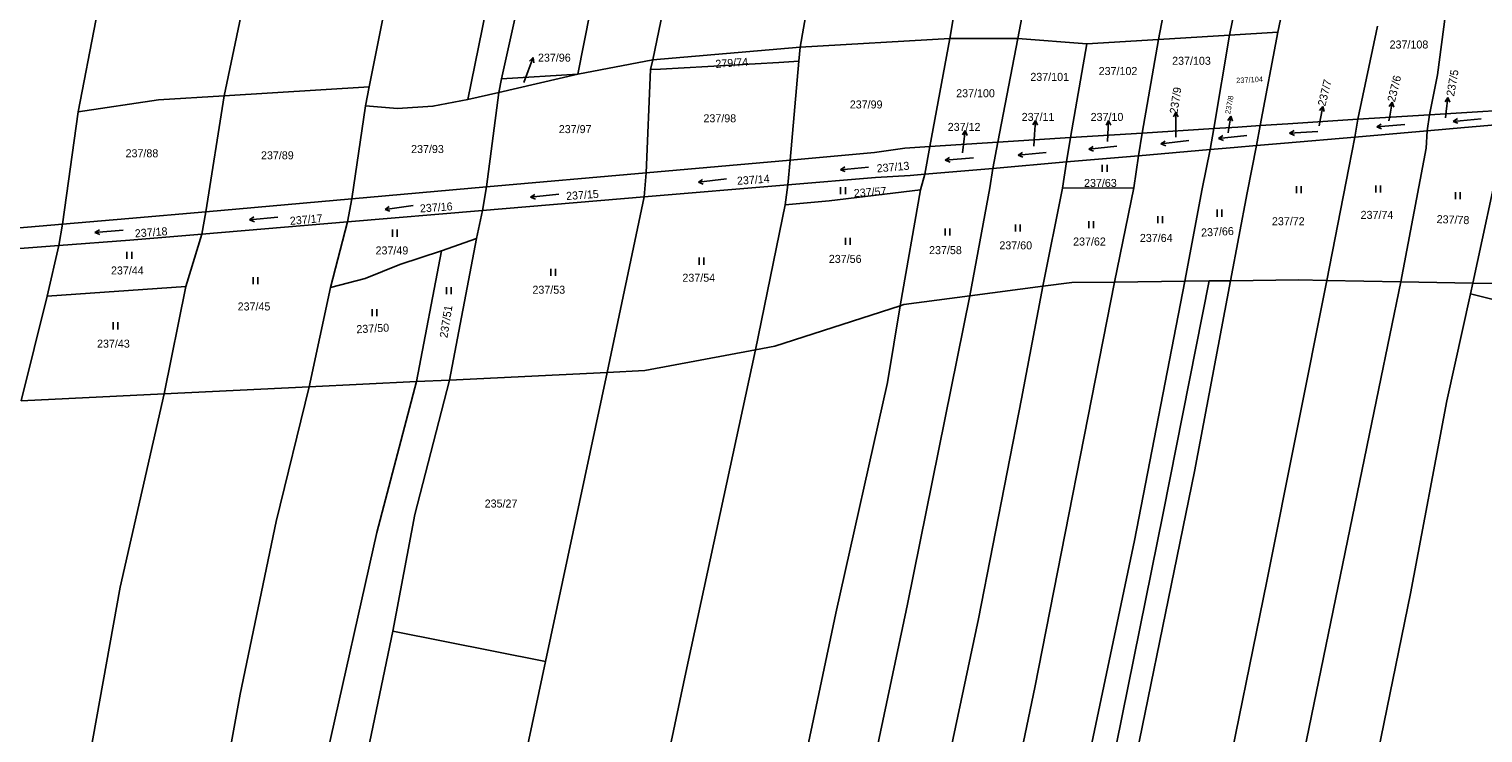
# Model space of a CAD drawing. Extents: x -755528 to -748832, y -1118122 to -1111095.
# Drawn here: x -753275.1 to -752966.3, y -1115050.1 to -1114900.7 of the extents above; entities that cross this region are included whole.
import ezdxf

# ---------------------------------------------------------------- set-up
doc = ezdxf.new("R2010")
doc.units = 0
for name, color, linetype in [('DZ_DO_PUPFL', 7, 'Continuous'), ('DZ_NAD_ZPF', 7, 'Continuous'), ('legenda barvy', 7, 'Continuous'), ('TZ_UMVŽST', 7, 'Continuous')]:
    doc.layers.add(name, color=color, linetype=linetype)

msp = doc.modelspace()

# ---------------------------------------------------------------- linework, layer by layer
at = {"layer": 'DZ_NAD_ZPF'}
for p, q in [((-753020.14, -1114901.94), (-753035.22, -1114902.86)), ((-753023.47, -1114921.78), (-753020.14, -1114901.94)), ((-753009.89, -1114901.31), (-753020.14, -1114901.94)), ((-753013.68, -1114921.16), (-753009.89, -1114901.31)), ((-752988.72, -1114900.02), (-752992.9, -1114919.83)), ((-753111.37, -1114904.48), (-753142.68, -1114907.21)), ((-753111.37, -1114904.48), (-753111.63, -1114907.51)), ((-753079.6, -1114902.69), (-753111.37, -1114904.48)), ((-753083.82, -1114925.62), (-753079.6, -1114902.69)), ((-753065.11, -1114902.7), (-753079.6, -1114902.69)), ((-753069.4, -1114924.7), (-753065.11, -1114902.7)), ((-753050.47, -1114903.79), (-753065.11, -1114902.7)), ((-753053.95, -1114923.72), (-753050.47, -1114903.79)), ((-753035.22, -1114902.86), (-753050.47, -1114903.79)), ((-753038.69, -1114922.75), (-753035.22, -1114902.86)), ((-753142.68, -1114907.21), (-753158.58, -1114910.23)), ((-753143.11, -1114909.28), (-753142.68, -1114907.21)), ((-753113.45, -1114928.48), (-753111.63, -1114907.51)), ((-753175.36, -1114914.1), (-753158.58, -1114910.23)), ((-753174.8, -1114911.22), (-753175.36, -1114914.1)), ((-753158.58, -1114910.23), (-753174.8, -1114911.22)), ((-753144.06, -1114931.18), (-753143.11, -1114909.28)), ((-753202.86, -1114912.96), (-753233.7, -1114914.85)), ((-753203.65, -1114916.94), (-753202.86, -1114912.96)), ((-753175.36, -1114914.1), (-753181.91, -1114915.59)), ((-753177.98, -1114934.18), (-753175.36, -1114914.1)), ((-753237.55, -1114939.45), (-753233.7, -1114914.85)), ((-753206.55, -1114936.71), (-753203.65, -1114916.94)), ((-753268.06, -1114942.09), (-753264.7, -1114918.22)), ((-752992.9, -1114919.83), (-752993.58, -1114923.59)), ((-752977.72, -1114918.87), (-752992.9, -1114919.83)), ((-752977.72, -1114918.87), (-752978.17, -1114922.25)), ((-753053.95, -1114923.72), (-753069.4, -1114924.7)), ((-753053.95, -1114923.72), (-753054.8, -1114928.89)), ((-753038.69, -1114922.75), (-753053.95, -1114923.72)), ((-753038.69, -1114922.75), (-753039.49, -1114927.56)), ((-753023.47, -1114921.78), (-753038.69, -1114922.75)), ((-753023.47, -1114921.78), (-753024.25, -1114926.24)), ((-753013.68, -1114921.16), (-753014.47, -1114925.4)), ((-752993.58, -1114923.59), (-752978.17, -1114922.25)), ((-753083.82, -1114925.62), (-753084.91, -1114931.5)), ((-753069.4, -1114924.7), (-753083.82, -1114925.62)), ((-753069.4, -1114924.7), (-753070.43, -1114930.25)), ((-753039.49, -1114927.56), (-753024.25, -1114926.24)), ((-753113.45, -1114928.48), (-753144.06, -1114931.18)), ((-753113.45, -1114928.48), (-753114, -1114933.76)), ((-753054.8, -1114928.89), (-753070.43, -1114930.25)), ((-753055.67, -1114934.43), (-753054.8, -1114928.89)), ((-753054.8, -1114928.89), (-753039.49, -1114927.56)), ((-753040.49, -1114934.41), (-753039.49, -1114927.56)), ((-753144.06, -1114931.18), (-753177.98, -1114934.18)), ((-753144.06, -1114931.18), (-753144.47, -1114936.32)), ((-753085.79, -1114934.81), (-753084.91, -1114931.5)), ((-753070.43, -1114930.25), (-753084.91, -1114931.5)), ((-753177.98, -1114934.18), (-753206.55, -1114936.71)), ((-753177.98, -1114934.18), (-753178.79, -1114939.2)), ((-753114, -1114933.76), (-753144.47, -1114936.32)), ((-753114.57, -1114937.97), (-753114, -1114933.76)), ((-753090.14, -1114959.41), (-753085.79, -1114934.81)), ((-753059.79, -1114955.29), (-753055.67, -1114934.43)), ((-753040.49, -1114934.41), (-753055.67, -1114934.43)), ((-753044.61, -1114954.39), (-753040.49, -1114934.41)), ((-753206.55, -1114936.71), (-753237.55, -1114939.45)), ((-753206.55, -1114936.71), (-753207.49, -1114941.6)), ((-753207.49, -1114941.6), (-753178.79, -1114939.2)), ((-753180.08, -1114945.16), (-753178.79, -1114939.2)), ((-753144.47, -1114936.32), (-753178.79, -1114939.2)), ((-753152.36, -1114973.59), (-753144.47, -1114936.32)), ((-753120.85, -1114968.78), (-753114.57, -1114937.97)), ((-753268.06, -1114942.09), (-753268.82, -1114946.63)), ((-753237.55, -1114939.45), (-753238.46, -1114944.2)), ((-753207.49, -1114941.6), (-753238.46, -1114944.2)), ((-753211.09, -1114955.55), (-753207.49, -1114941.6)), ((-753241.8, -1114955.31), (-753238.46, -1114944.2)), ((-753187.51, -1114947.77), (-753180.08, -1114945.16)), ((-753185.8, -1114975.2), (-753180.08, -1114945.16)), ((-753271.25, -1114957.38), (-753268.82, -1114946.63)), ((-753192.84, -1114975.54), (-753187.51, -1114947.77)), ((-753029.64, -1114954.22), (-753044.61, -1114954.39)), ((-753024.49, -1114954.16), (-753029.64, -1114954.22)), ((-753019.97, -1114954.11), (-753024.49, -1114954.16)), ((-752983.78, -1114954.34), (-752999.53, -1114954.05)), ((-752968.48, -1114954.62), (-752983.78, -1114954.34)), ((-752969, -1114956.89), (-752968.48, -1114954.62)), ((-752968.48, -1114954.62), (-752877, -1114956.31)), ((-753276.79, -1114979.6), (-753271.25, -1114957.38)), ((-753241.8, -1114955.31), (-753271.25, -1114957.38)), ((-753246.42, -1114978.13), (-753241.8, -1114955.31)), ((-753215.61, -1114976.64), (-753211.09, -1114955.55)), ((-753059.79, -1114955.29), (-753075.3, -1114957.32)), ((-752882.52, -1114978.45), (-752969, -1114956.89)), ((-753192.84, -1114975.54), (-753215.61, -1114976.64)), ((-753185.8, -1114975.2), (-753192.84, -1114975.54)), ((-753152.36, -1114973.59), (-753185.8, -1114975.2)), ((-753152.36, -1114973.59), (-753165.42, -1115034.99)), ((-753246.42, -1114978.13), (-753276.79, -1114979.6)), ((-753215.61, -1114976.64), (-753246.42, -1114978.13)), ((-753165.42, -1115034.99), (-753197.88, -1115028.53))]:
    msp.add_line(p, q, dxfattribs=at)
for points in [[(-753233.7, -1114914.85), (-753217.47, -1114837.62), (-753202.57, -1114766.08), (-753187.86, -1114697.77), (-753179.3, -1114653.45), (-753168.66, -1114603.79), (-753159.07, -1114559.65), (-753147.81, -1114508.95), (-753135.86, -1114458.16), (-753132.99, -1114439.92), (-753119.03, -1114364.97), (-753111.96, -1114332.42), (-753103.7, -1114299.27)], [(-753202.86, -1114912.96), (-753196.54, -1114881.1), (-753179.94, -1114804.74), (-753172.5, -1114766.42), (-753164.58, -1114726.12), (-753158.67, -1114699.35), (-753147.41, -1114652.62), (-753133.93, -1114587.99), (-753116.45, -1114506.67), (-753099.09, -1114423.78), (-753085.35, -1114358.88), (-753073.79, -1114304.82)], [(-753181.91, -1114915.59), (-753175, -1114881.47), (-753166.34, -1114839.97), (-753151.09, -1114766.66), (-753147.42, -1114748.58), (-753124.96, -1114651.85), (-753111.4, -1114582.84), (-753088.5, -1114479.57), (-753082.41, -1114445.74), (-753066.82, -1114371.23), (-753053.46, -1114308.6)], [(-753174.8, -1114911.22), (-753161.71, -1114852.23), (-753150.45, -1114796.76), (-753144.34, -1114766.73), (-753129.5, -1114697.6), (-753107.35, -1114597.98), (-753086.49, -1114497.53), (-753065.55, -1114394.92), (-753055.27, -1114343.56), (-753047.11, -1114309.78)], [(-753079.6, -1114902.69), (-753076.05, -1114881.54), (-753064.88, -1114833.75), (-753052.18, -1114771.34), (-753045.81, -1114738.36), (-753034.75, -1114687.32), (-753019.74, -1114619.92), (-753015.56, -1114599.37), (-753012.63, -1114588.54), (-752993.34, -1114497.31), (-752981.27, -1114437.96)], [(-753065.11, -1114902.7), (-753059.93, -1114875.41), (-753047.44, -1114822.82), (-753037.25, -1114772.48), (-753020.44, -1114690.21), (-752998.89, -1114596.67), (-752973.28, -1114483.85)], [(-753035.22, -1114902.86), (-753030.76, -1114879.49), (-753016.74, -1114820.75), (-753007.19, -1114774.77), (-752985.34, -1114668.69), (-752977.68, -1114633.44), (-752960.36, -1114552.68), (-752959.4, -1114549.77)], [(-753020.14, -1114901.94), (-753015.82, -1114880.89), (-753004.67, -1114831.04), (-752992.55, -1114775.89), (-752973.57, -1114684.2), (-752964.06, -1114637.71), (-752949.38, -1114576.99)], [(-753093.45, -1114602.23), (-753114.66, -1114693.33), (-753129.66, -1114766.9), (-753132.52, -1114779.2), (-753140.82, -1114819.96), (-753149.27, -1114863.31), (-753158.58, -1114910.23)], [(-753009.89, -1114901.31), (-752994.51, -1114828.43), (-752983.39, -1114776.59), (-752968.12, -1114704.27), (-752953.14, -1114634.3), (-752944.93, -1114599.94)], [(-753264.7, -1114918.22), (-753253.41, -1114859.98), (-753238.85, -1114790.7), (-753233.89, -1114765.73)], [(-753112.36, -1114767.73), (-753127.45, -1114836.94), (-753135.8, -1114873.94), (-753142.68, -1114907.21)], [(-753111.37, -1114904.48), (-753106.02, -1114874.19), (-753096.27, -1114830.76), (-753083.04, -1114769.21)], [(-752977.72, -1114918.87), (-752976.01, -1114910.37), (-752974.31, -1114897.47)], [(-753111.63, -1114907.51), (-753115.91, -1114907.77), (-753141.01, -1114909.15), (-753143.11, -1114909.28)], [(-753233.7, -1114914.85), (-753247.65, -1114915.71), (-753264.7, -1114918.22)], [(-753181.91, -1114915.59), (-753189.35, -1114917.06), (-753196.89, -1114917.54), (-753203.65, -1114916.94)], [(-752960.63, -1114917.78), (-752969.79, -1114918.36), (-752977.72, -1114918.87)], [(-753013.68, -1114921.16), (-753007.8, -1114920.78), (-752992.9, -1114919.83)], [(-752978.17, -1114922.25), (-752970.29, -1114921.57), (-752961.19, -1114920.78)], [(-753013.68, -1114921.16), (-753018.37, -1114921.46), (-753023.47, -1114921.78)], [(-752993.58, -1114923.59), (-753008.51, -1114924.88), (-753014.47, -1114925.4)], [(-752999.53, -1114954.05), (-752994.82, -1114930.13), (-752993.58, -1114923.59)], [(-752983.78, -1114954.34), (-752978.38, -1114925.93), (-752978.17, -1114922.25)], [(-753083.82, -1114925.62), (-753089.16, -1114925.96), (-753095.54, -1114926.9), (-753113.45, -1114928.48)], [(-753029.64, -1114954.22), (-753026, -1114934.62), (-753024.25, -1114926.24)], [(-753024.25, -1114926.24), (-753019.21, -1114925.81), (-753014.47, -1114925.4)], [(-753019.97, -1114954.11), (-753016.4, -1114935.42), (-753014.47, -1114925.4)], [(-752962, -1114924.6), (-752962.3, -1114926.03), (-752968.48, -1114954.62)], [(-753114, -1114933.76), (-753095.39, -1114932.2), (-753087.96, -1114931.76), (-753084.91, -1114931.5)], [(-753075.3, -1114957.32), (-753071.1, -1114934.41), (-753070.43, -1114930.25)], [(-753085.79, -1114934.81), (-753105.21, -1114937.15), (-753114.57, -1114937.97)], [(-753268.06, -1114942.09), (-753297.83, -1114944.61), (-753329.47, -1114947.29)], [(-753237.55, -1114939.45), (-753253.91, -1114940.89), (-753268.06, -1114942.09)], [(-753268.82, -1114946.63), (-753253.71, -1114945.48), (-753238.46, -1114944.2)], [(-753330.11, -1114951.34), (-753298.37, -1114948.9), (-753268.82, -1114946.63)], [(-753211.09, -1114955.55), (-753203.72, -1114953.66), (-753196.35, -1114950.65), (-753187.51, -1114947.77)], [(-753142.13, -1115429.02), (-753113.35, -1115286.36), (-753098.91, -1115217.03), (-753079.17, -1115125.01), (-753061.54, -1115040.52), (-753044.61, -1114954.39)], [(-753127.57, -1115428.31), (-753109.02, -1115343.31), (-753101.95, -1115305.88), (-753088.18, -1115233.5), (-753082.58, -1115208.88), (-753068.45, -1115142.47), (-753054.82, -1115077.88), (-753040.32, -1115009.27), (-753029.64, -1114954.22)], [(-753121.98, -1115428.03), (-753113.5, -1115387.63), (-753100.32, -1115322.58), (-753082.33, -1115233.25), (-753071.4, -1115180.79), (-753054.16, -1115101.79), (-753034.24, -1115003.46), (-753024.49, -1114954.16)], [(-753116.71, -1115427.77), (-753105.87, -1115373.64), (-753091.48, -1115301.38), (-753073.35, -1115211.52), (-753044.22, -1115075.89), (-753027.58, -1114994.65), (-753019.97, -1114954.11)], [(-753087.93, -1115385.88), (-753082.85, -1115356.32), (-753066.21, -1115276.38), (-753045.09, -1115175.92), (-753031.36, -1115111.65), (-753012.25, -1115017.92), (-752999.53, -1114954.05)], [(-753074.17, -1115385.26), (-753051.79, -1115280.52), (-753019.64, -1115128.38), (-752988.43, -1114977.02), (-752983.78, -1114954.34)], [(-753044.61, -1114954.39), (-753053.64, -1114954.49), (-753059.79, -1114955.29)], [(-752999.53, -1114954.05), (-753005.53, -1114953.94), (-753019.97, -1114954.11)], [(-753173.17, -1115430.68), (-753165.93, -1115395.55), (-753157.07, -1115356.14), (-753143.95, -1115293.66), (-753132.77, -1115235.62), (-753120.85, -1115176.85), (-753113.19, -1115143.15), (-753098.74, -1115070.99), (-753088.53, -1115022.81), (-753075.3, -1114957.32)], [(-753157.12, -1115429.79), (-753150.72, -1115394.51), (-753138.44, -1115339.24), (-753127.69, -1115287.77), (-753108.52, -1115190.37), (-753090.15, -1115104.28), (-753073.5, -1115025.89), (-753064.38, -1114979.16), (-753059.79, -1114955.29)], [(-753075.3, -1114957.32), (-753089.36, -1114959.16), (-753090.14, -1114959.41)], [(-752969, -1114956.89), (-752973.99, -1114979.61), (-752981.76, -1115020.52), (-753009.84, -1115157.88), (-753021.45, -1115211.53), (-753030.12, -1115252.85), (-753038.41, -1115288.88), (-753048.31, -1115334.89), (-753058.01, -1115384.53)], [(-753187.21, -1115431.46), (-753171.22, -1115354.98), (-753155.73, -1115279.97), (-753131.55, -1115155.67), (-753126.89, -1115133.75), (-753114.32, -1115074.76), (-753103.75, -1115024.73), (-753092.8, -1114975.75), (-753090.14, -1114959.41)], [(-753090.14, -1114959.41), (-753116.72, -1114968), (-753120.85, -1114968.78)], [(-753217.8, -1115433.14), (-753211.03, -1115398.97), (-753197.49, -1115336.74), (-753189.65, -1115300.03), (-753181.32, -1115255.47), (-753169.71, -1115196.97), (-753161.38, -1115155.22), (-753150.59, -1115108.84), (-753147.28, -1115092.2), (-753135.87, -1115038.32), (-753120.85, -1114968.78)], [(-753120.85, -1114968.78), (-753144.35, -1114973.2), (-753152.36, -1114973.59)], [(-753289.44, -1115425.79), (-753270.46, -1115352.32), (-753253.52, -1115265.95), (-753240.58, -1115200.65), (-753231.39, -1115149.23), (-753219.16, -1115098.09), (-753211.82, -1115054.59), (-753201.24, -1115007.6), (-753192.84, -1114975.54)], [(-753197.88, -1115028.53), (-753193.17, -1115003.76), (-753185.8, -1114975.2)], [(-753337.09, -1115412.19), (-753331.62, -1115395.18), (-753319.53, -1115340.8), (-753312.98, -1115305.64), (-753296.9, -1115224.92), (-753280.25, -1115143.21), (-753266.59, -1115079.29), (-753255.81, -1115019.21), (-753246.42, -1114978.13)], [(-753308.1, -1115421.53), (-753299.05, -1115385.38), (-753292.72, -1115360.89), (-753274.02, -1115263.55), (-753259.94, -1115189.91), (-753242.27, -1115107.78), (-753230.26, -1115041.93), (-753222.65, -1115005.26), (-753215.61, -1114976.64)], [(-753281.72, -1115426.85), (-753264.05, -1115355.01), (-753258.69, -1115328.65), (-753244.96, -1115255.46), (-753231.63, -1115186.8), (-753225.21, -1115157.64), (-753212.92, -1115100.88), (-753197.88, -1115028.53)], [(-753247.14, -1115431.84), (-753228.76, -1115342.49), (-753216.87, -1115281.25), (-753202.68, -1115205.58), (-753190.3, -1115146.78), (-753183.41, -1115119.5), (-753165.42, -1115034.99)]]:
    msp.add_lwpolyline(points, dxfattribs=at)
at = {"layer": 'legenda barvy'}
for p, q in [((-753169.12, -1114909.53), (-753168.045, -1114906.728)), ((-753168.045, -1114906.728), (-753168.871, -1114907.484)), ((-753168.045, -1114906.728), (-753167.936, -1114907.843)), ((-753170.06, -1114911.98), (-753169.12, -1114909.53)), ((-753000.347, -1114917.094), (-753001.03, -1114917.982)), ((-753000.92, -1114920.04), (-753000.347, -1114917.094)), ((-753000.347, -1114917.094), (-753000.047, -1114918.173)), ((-752985.609, -1114916.185), (-752986.276, -1114917.084)), ((-752986.13, -1114919.14), (-752985.609, -1114916.185)), ((-752985.609, -1114916.185), (-752985.29, -1114917.258)), ((-752973.774, -1114915.161), (-752974.393, -1114916.094)), ((-752974.14, -1114918.14), (-752973.774, -1114915.161)), ((-752973.774, -1114915.161), (-752973.399, -1114916.216)), ((-753061.351, -1114920.066), (-753061.92, -1114921.03)), ((-753061.56, -1114923.06), (-753061.351, -1114920.066)), ((-753061.351, -1114920.066), (-753060.921, -1114921.1)), ((-753045.843, -1114920.073), (-753046.395, -1114921.047)), ((-753046, -1114923.07), (-753045.843, -1114920.073)), ((-753045.843, -1114920.073), (-753045.395, -1114921.099)), ((-753031.6, -1114918.279), (-753032.101, -1114919.28)), ((-753031.6, -1114921.28), (-753031.6, -1114918.279)), ((-753031.6, -1114918.279), (-753031.099, -1114919.28)), ((-753019.891, -1114919.156), (-753020.542, -1114920.067)), ((-753020.36, -1114922.12), (-753019.891, -1114919.156)), ((-753019.891, -1114919.156), (-753019.553, -1114920.223)), ((-753001.15, -1114921.19), (-753000.92, -1114920.04)), ((-752986.3, -1114920.14), (-752986.13, -1114919.14)), ((-752974.31, -1114919.52), (-752974.14, -1114918.14)), ((-753076.284, -1114922.181), (-753076.903, -1114923.114)), ((-753076.65, -1114925.16), (-753076.284, -1114922.181)), ((-753076.284, -1114922.181), (-753075.909, -1114923.236)), ((-753061.71, -1114925.53), (-753061.56, -1114923.06)), ((-753046.09, -1114924.57), (-753046, -1114923.07)), ((-753031.58, -1114923.65), (-753031.6, -1114921.28)), ((-753020.45, -1114922.7), (-753020.36, -1114922.12)), ((-753076.88, -1114926.96), (-753076.65, -1114925.16))]:
    msp.add_line(p, q, dxfattribs=at)
at = {"layer": 'TZ_UMVŽST'}
for p, q in [((-752972.696, -1114920.264), (-752971.767, -1114919.68)), ((-752966.719, -1114919.741), (-752972.696, -1114920.264)), ((-752972.696, -1114920.264), (-752971.679, -1114920.679)), ((-753016.524, -1114923.27), (-753022.492, -1114923.897)), ((-753022.492, -1114923.897), (-753021.572, -1114923.296)), ((-753022.492, -1114923.897), (-753021.467, -1114924.293)), ((-753007.41, -1114922.802), (-753006.471, -1114922.234)), ((-753001.425, -1114922.383), (-753007.41, -1114922.802)), ((-753007.41, -1114922.802), (-753006.401, -1114923.234)), ((-752988.886, -1114921.454), (-752987.957, -1114920.87)), ((-752982.909, -1114920.931), (-752988.886, -1114921.454)), ((-752988.886, -1114921.454), (-752987.869, -1114921.869)), ((-753065.056, -1114927.424), (-753064.127, -1114926.84)), ((-753059.079, -1114926.901), (-753065.056, -1114927.424)), ((-753044.114, -1114925.56), (-753050.082, -1114926.187)), ((-753050.082, -1114926.187), (-753049.162, -1114925.586)), ((-753050.082, -1114926.187), (-753049.057, -1114926.583)), ((-753028.79, -1114924.328), (-753034.746, -1114925.059)), ((-753034.746, -1114925.059), (-753033.837, -1114924.442)), ((-753034.746, -1114925.059), (-753033.715, -1114925.438)), ((-753102.786, -1114930.524), (-753101.857, -1114929.94)), ((-753096.809, -1114930.001), (-753102.786, -1114930.524)), ((-753080.546, -1114928.534), (-753079.617, -1114927.95)), ((-753074.569, -1114928.011), (-753080.546, -1114928.534)), ((-753080.546, -1114928.534), (-753079.529, -1114928.949)), ((-753065.056, -1114927.424), (-753064.039, -1114927.839)), ((-753047.181, -1114930.96), (-753047.181, -1114929.46)), ((-753046.18, -1114930.96), (-753046.18, -1114929.46)), ((-753127.02, -1114932.468), (-753132.976, -1114933.199)), ((-753132.976, -1114933.199), (-753132.067, -1114932.582)), ((-753132.976, -1114933.199), (-753131.945, -1114933.578)), ((-753102.786, -1114930.524), (-753101.769, -1114930.939)), ((-753162.634, -1114935.74), (-753168.602, -1114936.367)), ((-753168.602, -1114936.367), (-753167.682, -1114935.766)), ((-753102.761, -1114935.71), (-753102.761, -1114934.21)), ((-753101.76, -1114935.71), (-753101.76, -1114934.21)), ((-753005.961, -1114935.54), (-753005.961, -1114934.04)), ((-753004.96, -1114935.54), (-753004.96, -1114934.04)), ((-752989.101, -1114935.36), (-752989.101, -1114933.86)), ((-752988.1, -1114935.36), (-752988.1, -1114933.86)), ((-752972.181, -1114936.79), (-752972.181, -1114935.29)), ((-752971.18, -1114936.79), (-752971.18, -1114935.29)), ((-753193.567, -1114938.146), (-753199.509, -1114938.981)), ((-753199.509, -1114938.981), (-753198.611, -1114938.349)), ((-753199.509, -1114938.981), (-753198.472, -1114939.342)), ((-753168.602, -1114936.367), (-753167.577, -1114936.763)), ((-753022.801, -1114940.51), (-753022.801, -1114939.01)), ((-753021.8, -1114940.51), (-753021.8, -1114939.01)), ((-753228.296, -1114941.154), (-753227.367, -1114940.57)), ((-753222.319, -1114940.631), (-753228.296, -1114941.154)), ((-753228.296, -1114941.154), (-753227.279, -1114941.569)), ((-753065.621, -1114943.67), (-753065.621, -1114942.17)), ((-753064.62, -1114943.67), (-753064.62, -1114942.17)), ((-753050.061, -1114942.94), (-753050.061, -1114941.44)), ((-753049.06, -1114942.94), (-753049.06, -1114941.44)), ((-753035.381, -1114941.89), (-753035.381, -1114940.39)), ((-753034.38, -1114941.89), (-753034.38, -1114940.39)), ((-753261.126, -1114943.864), (-753260.197, -1114943.28)), ((-753255.149, -1114943.341), (-753261.126, -1114943.864)), ((-753261.126, -1114943.864), (-753260.109, -1114944.279)), ((-753197.941, -1114944.75), (-753197.941, -1114943.25)), ((-753196.94, -1114944.75), (-753196.94, -1114943.25)), ((-753101.761, -1114946.48), (-753101.761, -1114944.98)), ((-753100.76, -1114946.48), (-753100.76, -1114944.98)), ((-753080.591, -1114944.49), (-753080.591, -1114942.99)), ((-753079.59, -1114944.49), (-753079.59, -1114942.99)), ((-753254.331, -1114949.48), (-753254.331, -1114947.98)), ((-753253.33, -1114949.48), (-753253.33, -1114947.98)), ((-753164.331, -1114953.06), (-753164.331, -1114951.56)), ((-753163.33, -1114953.06), (-753163.33, -1114951.56)), ((-753132.791, -1114950.7), (-753132.791, -1114949.2)), ((-753131.79, -1114950.7), (-753131.79, -1114949.2)), ((-753227.551, -1114954.85), (-753227.551, -1114953.35)), ((-753226.55, -1114954.85), (-753226.55, -1114953.35)), ((-753186.471, -1114956.98), (-753186.471, -1114955.48)), ((-753185.47, -1114956.98), (-753185.47, -1114955.48)), ((-753202.261, -1114961.63), (-753202.261, -1114960.13)), ((-753201.26, -1114961.63), (-753201.26, -1114960.13)), ((-753257.281, -1114964.43), (-753257.281, -1114962.93)), ((-753256.28, -1114964.43), (-753256.28, -1114962.93))]:
    msp.add_line(p, q, dxfattribs=at)

# ---------------------------------------------------------------- texts
at = {"layer": 'DZ_DO_PUPFL'}
for s, p in [('237/108', (-752986.17, -1114904.79)), ('237/96', (-753167.04, -1114907.58)), ('237/103', (-753032.36, -1114908.25)), ('237/101', (-753062.47, -1114911.66)), ('237/102', (-753047.96, -1114910.43)), ('237/100', (-753078.22, -1114915.14)), ('237/99', (-753100.82, -1114917.52)), ('237/98', (-753131.9, -1114920.46)), ('237/12', (-753080.017, -1114922.29)), ('237/11', (-753064.31, -1114920.17)), ('237/10', (-753049.667, -1114920.17)), ('237/97', (-753162.62, -1114922.76)), ('237/88', (-753254.63, -1114927.89)), ('237/89', (-753225.87, -1114928.32)), ('237/93', (-753193.99, -1114926.99)), ('237/63', (-753051.07, -1114934.19)), ('237/74', (-752992.33, -1114940.97)), ('237/72', (-753011.16, -1114942.32)), ('237/62', (-753053.39, -1114946.63)), ('237/64', (-753039.21, -1114945.87)), ('237/49', (-753201.54, -1114948.52)), ('237/56', (-753105.27, -1114950.32)), ('237/58', (-753083.98, -1114948.46)), ('237/60', (-753069.05, -1114947.44)), ('237/44', (-753257.73, -1114952.78)), ('237/54', (-753136.37, -1114954.32)), ('237/53', (-753168.22, -1114956.87)), ('237/45', (-753230.83, -1114960.42)), ('237/43', (-753260.69, -1114968.32)), ('235/27', (-753178.36, -1115002.27))]:
    msp.add_text(s, height=1.7, dxfattribs=at).set_placement(p)
for s, height, rotation, p in [('279/74', 1.7, 4, (-753129.3, -1114908.927)), ('237/104', 1.139, 3, (-753018.72, -1114912.158)), ('237/7', 1.7, 76, (-752999.833, -1114917.156)), ('237/6', 1.7, 76, (-752985.053, -1114916.276)), ('237/5', 1.7, 80, (-752972.485, -1114915.036)), ('237/9', 1.7, 81, (-753031.252, -1114918.758)), ('237/8', 1.139, 79, (-753020.042, -1114918.778)), ('237/13', 1.7, 5, (-753095.025, -1114931.116)), ('237/14', 1.7, 4, (-753124.72, -1114933.747)), ('237/15', 1.7, 4, (-753161.01, -1114936.977)), ('237/57', 1.7, 4, (-753099.91, -1114936.367)), ('237/16', 1.7, 4, (-753192.06, -1114939.617)), ('237/17', 1.7, 5, (-753219.655, -1114942.256)), ('237/78', 1.7, 358, (-752976.209, -1114941.859)), ('237/18', 1.7, 4, (-753252.61, -1114944.907)), ('237/66', 1.7, 3, (-753026.165, -1114944.738)), ('237/51', 1.7, 81, (-753186.28, -1114966.342)), ('237/50', 1.7, 3, (-753205.565, -1114965.268))]:
    msp.add_text(s, height=height, rotation=rotation, dxfattribs=at).set_placement(p)

doc.saveas('drawing.dxf')
